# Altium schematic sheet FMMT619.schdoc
size 127 x 101 mm
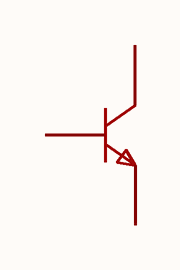
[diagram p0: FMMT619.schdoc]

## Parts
Q?  fmmt619_c53071  [SOT-23-3_L2.9-W1.3-P1.90-LS2.4-BR]  (value not drawn)

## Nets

Not connected (* = marked no-connect by the designer): Q? 1(B) 2(E) 3(C)

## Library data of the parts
Q? = fmmt619_c53071: 晶体管类型:NPN;集电极电流(Ic):2A;集射极击穿电压(Vceo):50V;耗散功率(Pd):350mW;直流电流增益(hFE):200;; Manufacturer: CJ(江苏长电/长晶); AddInBom: yes; ModelId: c62791f0466c4ae2a892c056b845b0ca; ModelName: SOT-23-3P_L2.9-W1.3-H1.0-LS2.4-P0.95; ModelTransform: 98.425,114.173,0,180,0,0,0.0005,-0.0005,0; type: NPN; Current - Collector(Ic): 2A; Collector - Emitter Voltage VCEO: 50V; Pd - Power Dissipation: 350mW; DC Current Gain: 200; Transition frequency(fT): 100MHz; Current - Collector Cutoff: 100nA; Vce Saturation(VCE(sat)): 220mV; Emitter-Base Voltage(Vebo): 5V; Number: 1个NPN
